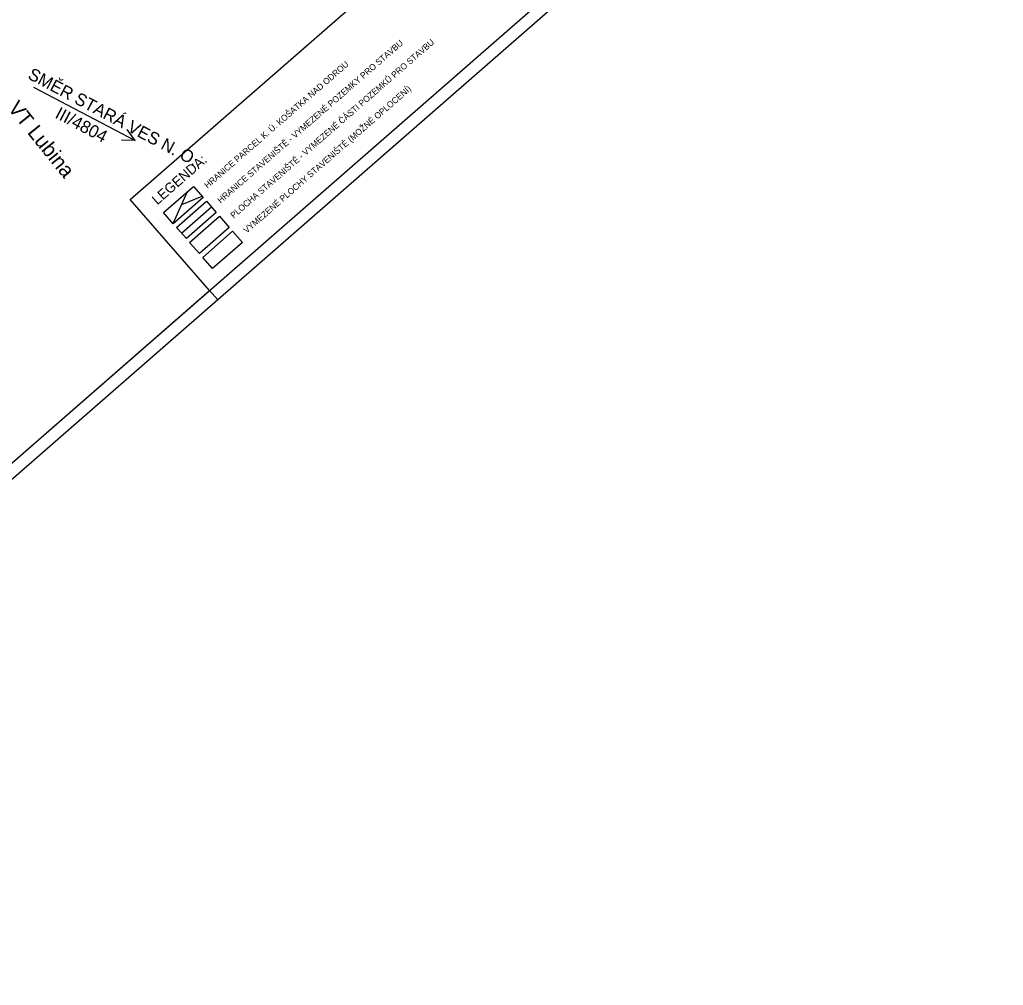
# Model space of a CAD drawing. Extents: x -482105 to -477964, y -1113879 to -1109998.
# Drawn here: x -479945 to -477964, y -1113879 to -1111934 of the extents above; entities that cross this region are included whole.
import ezdxf

# ---------------------------------------------------------------- set-up
doc = ezdxf.new("R2010")
doc.units = 0
for name, color, linetype in [('legenda', 7, 'Continuous'), ('popis', 7, 'Continuous'), ('rozpiska', 7, 'Continuous')]:
    doc.layers.add(name, color=color, linetype=linetype)

msp = doc.modelspace()

# ---------------------------------------------------------------- linework, layer by layer
at = {"layer": 'legenda'}
for p, q in [((-479636, -1112344.4), (-479607.1, -1112280.3)), ((-479618.6, -1112305.9), (-479577.5, -1112289.7)), ((-479619.1, -1112363.7), (-479558.8, -1112311.1))]:
    msp.add_line(p, q, dxfattribs=at)
for points in [[(-481125.9, -1113843.4), (-479562.4, -1112479.2), (-479722.1, -1112296.2), (-478939.3, -1111613.2), (-479240.6, -1111267.9), (-478575.9, -1110687.9), (-479060.3, -1110136.7), (-481297.1, -1112088.2), (-481198.7, -1112201), (-481971, -1112874.8)], [(-479575.2, -1112292.3), (-479635.5, -1112344.9), (-479655.2, -1112322.3), (-479595, -1112269.7)], [(-479548.9, -1112322.4), (-479609.2, -1112375), (-479628.9, -1112352.4), (-479568.7, -1112299.8)], [(-479522.6, -1112352.5), (-479582.9, -1112405.1), (-479602.6, -1112382.5), (-479542.4, -1112329.9)], [(-479496.3, -1112382.7), (-479556.6, -1112435.3), (-479576.3, -1112412.7), (-479516.1, -1112360.1)]]:
    msp.add_lwpolyline(points, close=True, dxfattribs=at)
at = {"layer": 'popis'}
for p, q in [((-479917.2, -1112069.7), (-479712.4, -1112177.5)), ((-479712.4, -1112177.5), (-479728.7, -1112155.3)), ((-479712.4, -1112177.5), (-479740, -1112176.7))]:
    msp.add_line(p, q, dxfattribs=at)
at = {"layer": 'rozpiska'}
msp.add_line((-479546, -1112498), (-479562.4, -1112479.2), dxfattribs=at)
msp.add_line((-479546, -1112498), (-479562.4, -1112479.2), dxfattribs=at)
msp.add_line((-479546, -1112498), (-479562.4, -1112479.2), dxfattribs=at)
for points in [[(-477963.6, -1111117.5), (-481128.3, -1113878.7), (-482104.7, -1112759.7), (-478939.9, -1109998.4)], [(-477998.9, -1111115.1), (-481125.9, -1113843.4), (-482069.4, -1112762.1), (-478942.3, -1110033.7)]]:
    msp.add_lwpolyline(points, close=True, dxfattribs=at)

# ---------------------------------------------------------------- texts
at = {"layer": 'legenda'}
for s, height, p in [('HRANICE STAVENIŠTĚ - VYMEZENÉ POZEMKY PRO STAVBU', 12.5, (-479540.1, -1112304.7)), ('PLOCHA STAVENIŠTĚ - VYMEZENÉ ČÁSTI POZEMKŮ PRO STAVBU', 12.5, (-479513.8, -1112334.9)), ('HRANICE PARCEL K. Ú. KOŠATKA NAD ODROU', 12.5, (-479566.4, -1112274.6)), ('VYMEZENÉ PLOCHY STAVENIŠTĚ (MOŽNÉ OPLOCENÍ)', 12.5, (-479487.5, -1112365)), ('LEGENDA:', 20, (-479667.7, -1112308))]:
    msp.add_text(s, height=height, rotation=41.0974, dxfattribs=at).set_placement(p)
at = {"layer": 'popis'}
for s, height, rotation, p in [('SMĚR STARÁ VES N. O.', 25, 332.1472, (-479930.4, -1112051.7)), ('VT Lubina', 30, 308.8959, (-479970, -1112113)), ('III/4804', 25, 332.1472, (-479875.5, -1112130.6))]:
    msp.add_text(s, height=height, rotation=rotation, dxfattribs=at).set_placement(p)

doc.saveas('drawing.dxf')
